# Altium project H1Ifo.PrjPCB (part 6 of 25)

## Sheet IfoIsc2A.SchDoc: D1800185
size C; Engineer: Daniel Sigg; DocumentNumber: 5; Revision: 4; SheetNumber: 5; SheetTotal: 11
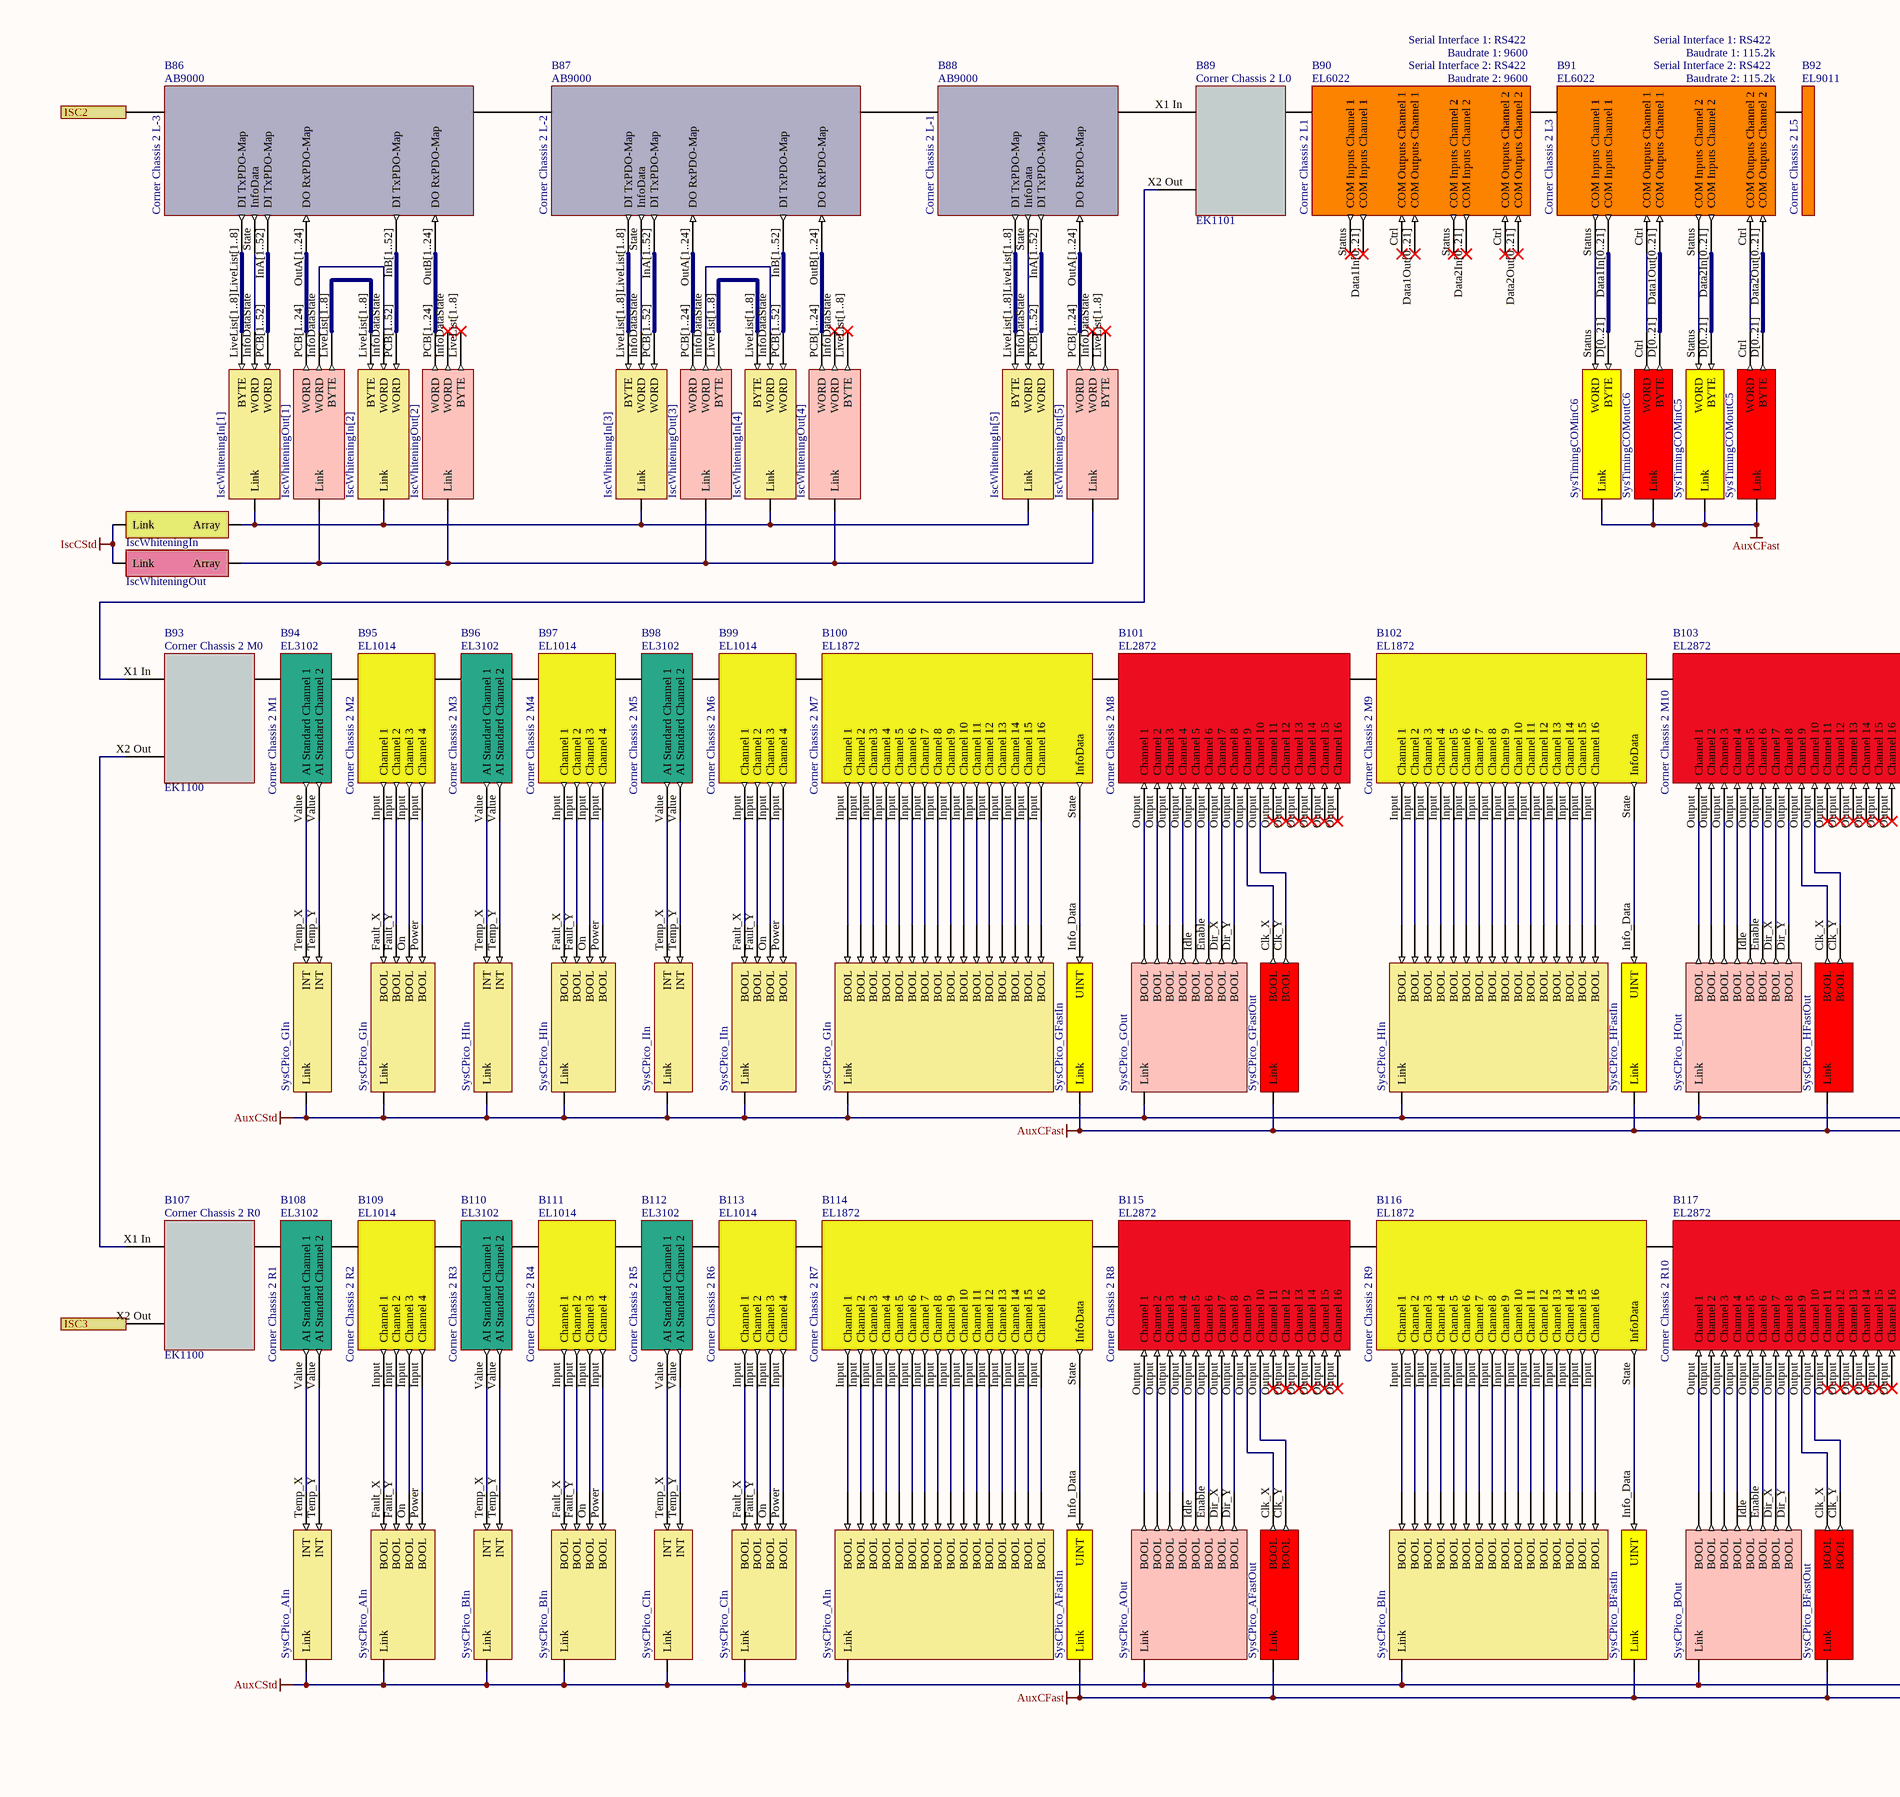
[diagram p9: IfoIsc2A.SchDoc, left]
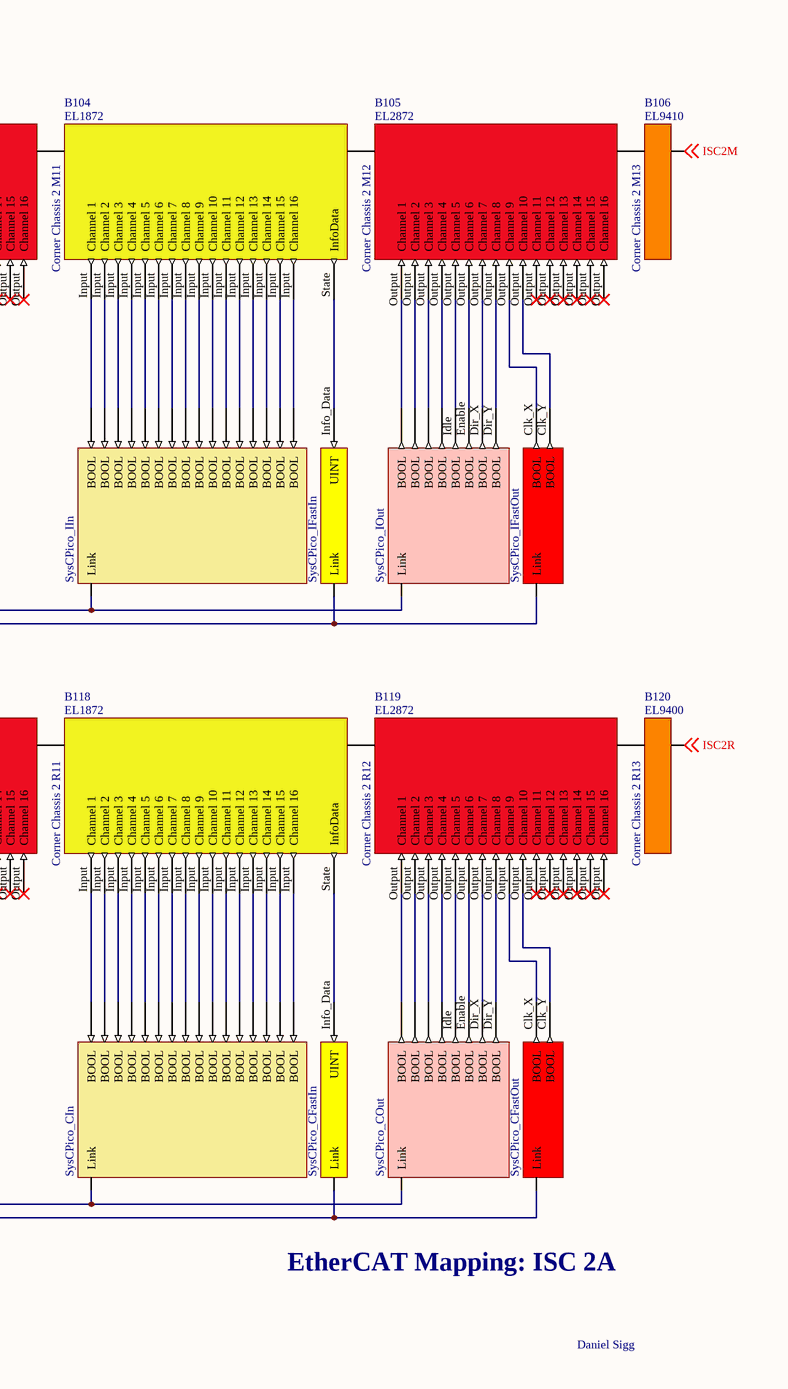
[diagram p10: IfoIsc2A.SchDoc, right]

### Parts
B86  Corner Chassis 2 L-3  Part Number: AB9000  (mechanical)
B87  Corner Chassis 2 L-2  Part Number: AB9000  (mechanical)
B88  Corner Chassis 2 L-1  Part Number: AB9000  (mechanical)
B89  Corner Chassis 2 L0  Part Number: EK1101  (mechanical)
B90  Corner Chassis 2 L1  Part Number: EL6022  Baudrate 1: 9600  Serial Interface 1: RS422  (mechanical)
B91  Corner Chassis 2 L3  Part Number: EL6022  Baudrate 1: 115.2k  Serial Interface 1: RS422  (mechanical)
B92  Corner Chassis 2 L5  Part Number: EL9011  (mechanical)
B93  Corner Chassis 2 M0  Part Number: EK1100  (mechanical)
B94  Corner Chassis 2 M1  Part Number: EL3102  (mechanical)
B95  Corner Chassis 2 M2  Part Number: EL1014  (mechanical)
B96  Corner Chassis 2 M3  Part Number: EL3102  (mechanical)
B97  Corner Chassis 2 M4  Part Number: EL1014  (mechanical)
B98  Corner Chassis 2 M5  Part Number: EL3102  (mechanical)
B99  Corner Chassis 2 M6  Part Number: EL1014  (mechanical)
B100  Corner Chassis 2 M7  Part Number: EL1872  (mechanical)
B101  Corner Chassis 2 M8  Part Number: EL2872  (mechanical)
B102  Corner Chassis 2 M9  Part Number: EL1872  (mechanical)
B103  Corner Chassis 2 M10  Part Number: EL2872  (mechanical)
B104  Corner Chassis 2 M11  Part Number: EL1872  (mechanical)
B105  Corner Chassis 2 M12  Part Number: EL2872  (mechanical)
B106  Corner Chassis 2 M13  Part Number: EL9410  (mechanical)
B107  Corner Chassis 2 R0  Part Number: EK1100  (mechanical)
B108  Corner Chassis 2 R1  Part Number: EL3102  (mechanical)
B109  Corner Chassis 2 R2  Part Number: EL1014  (mechanical)
B110  Corner Chassis 2 R3  Part Number: EL3102  (mechanical)
B111  Corner Chassis 2 R4  Part Number: EL1014  (mechanical)
B112  Corner Chassis 2 R5  Part Number: EL3102  (mechanical)
B113  Corner Chassis 2 R6  Part Number: EL1014  (mechanical)
B114  Corner Chassis 2 R7  Part Number: EL1872  (mechanical)
B115  Corner Chassis 2 R8  Part Number: EL2872  (mechanical)
B116  Corner Chassis 2 R9  Part Number: EL1872  (mechanical)
B117  Corner Chassis 2 R10  Part Number: EL2872  (mechanical)
B118  Corner Chassis 2 R11  Part Number: EL1872  (mechanical)
B119  Corner Chassis 2 R12  Part Number: EL2872  (mechanical)
B120  Corner Chassis 2 R13  Part Number: EL9400  (mechanical)
V49  SysCPico_GIn  (parts A,B,C of 3)  (no BOM)
V50  SysCPico_HIn  (parts A,B,C of 3)  (no BOM)
V51  SysCPico_IIn  (parts A,B,C of 3)  (no BOM)
V62  SysCPico_AIn  (parts A,B,C of 3)  (no BOM)
V63  SysCPico_BIn  (parts A,B,C of 3)  (no BOM)
V64  SysCPico_CIn  (parts A,B,C of 3)  (no BOM)
V152  IscWhiteningIn[1]  (no BOM)
V155  IscWhiteningOut[1]  (no BOM)
V156  IscWhiteningIn[2]  (no BOM)
V157  IscWhiteningOut[2]  (no BOM)
V158  IscWhiteningIn[3]  (no BOM)
V159  IscWhiteningOut[3]  (no BOM)
V160  IscWhiteningIn[4]  (no BOM)
V161  IscWhiteningOut[4]  (no BOM)
V162  IscWhiteningIn[5]  (no BOM)
V163  IscWhiteningOut[5]  (no BOM)
V164  IscWhiteningIn  (no BOM)
V165  SysTimingCOMinC6  (no BOM)
V166  SysTimingCOMoutC6  (no BOM)
V167  SysTimingCOMinC5  (no BOM)
V168  SysTimingCOMoutC5  (no BOM)
V170  IscWhiteningOut  (no BOM)
V172  SysCPico_GFastIn  (no BOM)
V173  SysCPico_GOut  (no BOM)
V174  SysCPico_GFastOut  (no BOM)
V175  SysCPico_HFastIn  (no BOM)
V178  SysCPico_HOut  (no BOM)
V179  SysCPico_HFastOut  (no BOM)
V180  SysCPico_IFastIn  (no BOM)
V181  SysCPico_IOut  (no BOM)
V182  SysCPico_IFastOut  (no BOM)
V183  SysCPico_AFastIn  (no BOM)
V184  SysCPico_AOut  (no BOM)
V185  SysCPico_AFastOut  (no BOM)
V186  SysCPico_BFastIn  (no BOM)
V187  SysCPico_BOut  (no BOM)
V188  SysCPico_BFastOut  (no BOM)
V189  SysCPico_CFastIn  (no BOM)
V190  SysCPico_COut  (no BOM)
V191  SysCPico_CFastOut  (no BOM)

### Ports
ISC2, ISC3

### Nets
AuxCFast: V165.?1(Link) V166.?1(Link) V167.?1(Link) V168.?1(Link) V172.0(Link) V174.0(Link) V175.0(Link) V179.0(Link) V180.0(Link) V182.0(Link) V183.0(Link) V185.0(Link) V186.0(Link) V188.0(Link) V189.0(Link) V191.0(Link)
AuxCStd: V49.0(Link) V49.1(Link) V49.2(Link) V50.0(Link) V50.1(Link) V50.2(Link) V51.0(Link) V51.1(Link) V51.2(Link) V62.0(Link) V62.1(Link) V62.2(Link) V63.0(Link) V63.1(Link) V63.2(Link) V64.0(Link) V64.1(Link) V64.2(Link) V173.0(Link) V178.0(Link) V181.0(Link) V184.0(Link) V187.0(Link) V190.0(Link)
IscCStd: V164.?1(Link) V170.?1(Link)
ISC2M: B106.Ebus(B) ; off-sheet ISC2M
ISC2R: B120.Ebus(B) ; off-sheet ISC2R
NetB70_X2 Out: B86.?2(A) ; port ISC2
NetB86_?1: B86.?1(B) B87.?2(A)
NetB86_InA[1..52]: B86.InA[1..52](DI_TxPDO-Map) V152.PCB[1..52](WORD)
NetB86_InB[1..52]: B86.InB[1..52](DI_TxPDO-Map) V156.PCB[1..52](WORD)
NetB86_LiveList[1..8]: B86.LiveList[1..8](DI_TxPDO-Map) V152.LiveList[1..8](BYTE)
NetB86_OutA[1..24]: B86.OutA[1..24](DO_RxPDO-Map) V155.PCB[1..24](WORD)
NetB86_OutB[1..24]: B86.OutB[1..24](DO_RxPDO-Map) V157.PCB[1..24](WORD)
NetB86_State: B86.State(InfoData) V152.InfoDataState(WORD)
NetB87_?1: B87.?1(B) B88.?2(A)
NetB87_InA[1..52]: B87.InA[1..52](DI_TxPDO-Map) V158.PCB[1..52](WORD)
NetB87_InB[1..52]: B87.InB[1..52](DI_TxPDO-Map) V160.PCB[1..52](WORD)
NetB87_LiveList[1..8]: B87.LiveList[1..8](DI_TxPDO-Map) V158.LiveList[1..8](BYTE)
NetB87_OutA[1..24]: B87.OutA[1..24](DO_RxPDO-Map) V159.PCB[1..24](WORD)
NetB87_OutB[1..24]: B87.OutB[1..24](DO_RxPDO-Map) V161.PCB[1..24](WORD)
NetB87_State: B87.State(InfoData) V158.InfoDataState(WORD)
NetB88_?1: B88.?1(B) B89.X1_In(A)
NetB88_InA[1..52]: B88.InA[1..52](DI_TxPDO-Map) V162.PCB[1..52](WORD)
NetB88_LiveList[1..8]: B88.LiveList[1..8](DI_TxPDO-Map) V162.LiveList[1..8](BYTE)
NetB88_OutA[1..24]: B88.OutA[1..24](DO_RxPDO-Map) V163.PCB[1..24](WORD)
NetB88_State: B88.State(InfoData) V162.InfoDataState(WORD)
NetB89_Ebus: B89.Ebus(B) B90.Ebus(A)
NetB89_X2 Out: B89.X2_Out(C) B93.X1_In(A)
NetB90_Ebus: B90.Ebus(B) B91.Ebus(A)
NetB91_Ctrl: B91.Ctrl(COM_Outputs_Channel_1) V166.Ctrl(WORD)
NetB91_Ctrl: B91.Ctrl(COM_Outputs_Channel_2) V168.Ctrl(WORD)  [a separate net that carries the same name]
NetB91_Data1In[0..21]: B91.Data1In[0..21](COM_Inputs_Channel_1) V165.D[0..21](BYTE)
NetB91_Data1Out[0..21]: B91.Data1Out[0..21](COM_Outputs_Channel_1) V166.D[0..21](BYTE)
NetB91_Data2In[0..21]: B91.Data2In[0..21](COM_Inputs_Channel_2) V167.D[0..21](BYTE)
NetB91_Data2Out[0..21]: B91.Data2Out[0..21](COM_Outputs_Channel_2) V168.D[0..21](BYTE)
NetB91_Ebus: B91.Ebus(B) B92.Ebus(A)
NetB91_Status: B91.Status(COM_Inputs_Channel_1) V165.Status(WORD)
NetB91_Status: B91.Status(COM_Inputs_Channel_2) V167.Status(WORD)  [a separate net that carries the same name]
NetB93_Ebus: B93.Ebus(B) B94.Ebus(A)
NetB93_X2 Out: B93.X2_Out(C) B107.X1_In(A)
NetB94_Ebus: B94.Ebus(B) B95.Ebus(A)
NetB94_Value: B94.Value(AI_Standard_Channel_1) V49.Temp_X(INT)
NetB94_Value: B94.Value(AI_Standard_Channel_2) V49.Temp_Y(INT)  [a separate net that carries the same name]
NetB95_Ebus: B95.Ebus(B) B96.Ebus(A)
NetB95_Input: B95.Input(Channel_1) V49.Fault_X(BOOL)
NetB95_Input: B95.Input(Channel_2) V49.Fault_Y(BOOL)  [a separate net that carries the same name]
NetB95_Input: B95.Input(Channel_3) V49.On(BOOL)  [a separate net that carries the same name]
NetB95_Input: B95.Input(Channel_4) V49.Power(BOOL)  [a separate net that carries the same name]
NetB96_Ebus: B96.Ebus(B) B97.Ebus(A)
NetB96_Value: B96.Value(AI_Standard_Channel_1) V50.Temp_X(INT)
NetB96_Value: B96.Value(AI_Standard_Channel_2) V50.Temp_Y(INT)  [a separate net that carries the same name]
NetB97_Ebus: B97.Ebus(B) B98.Ebus(A)
NetB97_Input: B97.Input(Channel_1) V50.Fault_X(BOOL)
NetB97_Input: B97.Input(Channel_2) V50.Fault_Y(BOOL)  [a separate net that carries the same name]
NetB97_Input: B97.Input(Channel_3) V50.On(BOOL)  [a separate net that carries the same name]
NetB97_Input: B97.Input(Channel_4) V50.Power(BOOL)  [a separate net that carries the same name]
NetB98_Ebus: B98.Ebus(B) B99.Ebus(A)
NetB98_Value: B98.Value(AI_Standard_Channel_1) V51.Temp_X(INT)
NetB98_Value: B98.Value(AI_Standard_Channel_2) V51.Temp_Y(INT)  [a separate net that carries the same name]
NetB99_Ebus: B99.Ebus(B) B100.Ebus(A)
NetB99_Input: B99.Input(Channel_1) V51.Fault_X(BOOL)
NetB99_Input: B99.Input(Channel_2) V51.Fault_Y(BOOL)  [a separate net that carries the same name]
NetB99_Input: B99.Input(Channel_3) V51.On(BOOL)  [a separate net that carries the same name]
NetB99_Input: B99.Input(Channel_4) V51.Power(BOOL)  [a separate net that carries the same name]
NetB100_Ebus: B100.Ebus(B) B101.Ebus(A)
NetB100_Input: B100.Input(Channel_1) V49.MotorX1(BOOL)
NetB100_Input: B100.Input(Channel_2) V49.MotorX2(BOOL)  [a separate net that carries the same name]
NetB100_Input: B100.Input(Channel_3) V49.MotorX3(BOOL)  [a separate net that carries the same name]
NetB100_Input: B100.Input(Channel_4) V49.MotorX4(BOOL)  [a separate net that carries the same name]
NetB100_Input: B100.Input(Channel_5) V49.MotorX5(BOOL)  [a separate net that carries the same name]
NetB100_Input: B100.Input(Channel_6) V49.MotorX6(BOOL)  [a separate net that carries the same name]
NetB100_Input: B100.Input(Channel_7) V49.MotorX7(BOOL)  [a separate net that carries the same name]
NetB100_Input: B100.Input(Channel_8) V49.MotorX8(BOOL)  [a separate net that carries the same name]
NetB100_Input: B100.Input(Channel_9) V49.MotorY1(BOOL)  [a separate net that carries the same name]
NetB100_Input: B100.Input(Channel_10) V49.MotorY2(BOOL)  [a separate net that carries the same name]
NetB100_Input: B100.Input(Channel_11) V49.MotorY3(BOOL)  [a separate net that carries the same name]
NetB100_Input: B100.Input(Channel_12) V49.MotorY4(BOOL)  [a separate net that carries the same name]
NetB100_Input: B100.Input(Channel_13) V49.MotorY5(BOOL)  [a separate net that carries the same name]
NetB100_Input: B100.Input(Channel_14) V49.MotorY6(BOOL)  [a separate net that carries the same name]
NetB100_Input: B100.Input(Channel_15) V49.MotorY7(BOOL)  [a separate net that carries the same name]
NetB100_Input: B100.Input(Channel_16) V49.MotorY8(BOOL)  [a separate net that carries the same name]
NetB100_State: B100.State(InfoData) V172.Info_Data(UINT)
NetB101_Ebus: B101.Ebus(B) B102.Ebus(A)
NetB101_Output: B101.Output(Channel_1) V173.MOTOR3(BOOL)
NetB101_Output: B101.Output(Channel_2) V173.MOTOR2(BOOL)  [a separate net that carries the same name]
NetB101_Output: B101.Output(Channel_3) V173.MOTOR1(BOOL)  [a separate net that carries the same name]
NetB101_Output: B101.Output(Channel_4) V173.MOTOR4(BOOL)  [a separate net that carries the same name]
NetB101_Output: B101.Output(Channel_5) V173.Idle(BOOL)  [a separate net that carries the same name]
NetB101_Output: B101.Output(Channel_6) V173.Enable(BOOL)  [a separate net that carries the same name]
NetB101_Output: B101.Output(Channel_7) V173.Dir_X(BOOL)  [a separate net that carries the same name]
NetB101_Output: B101.Output(Channel_8) V173.Dir_Y(BOOL)  [a separate net that carries the same name]
NetB101_Output: B101.Output(Channel_9) V174.Clk_X(BOOL)  [a separate net that carries the same name]
NetB101_Output: B101.Output(Channel_10) V174.Clk_Y(BOOL)  [a separate net that carries the same name]
NetB102_Ebus: B102.Ebus(B) B103.Ebus(A)
NetB102_Input: B102.Input(Channel_1) V50.MotorX1(BOOL)
NetB102_Input: B102.Input(Channel_2) V50.MotorX2(BOOL)  [a separate net that carries the same name]
NetB102_Input: B102.Input(Channel_3) V50.MotorX3(BOOL)  [a separate net that carries the same name]
NetB102_Input: B102.Input(Channel_4) V50.MotorX4(BOOL)  [a separate net that carries the same name]
NetB102_Input: B102.Input(Channel_5) V50.MotorX5(BOOL)  [a separate net that carries the same name]
NetB102_Input: B102.Input(Channel_6) V50.MotorX6(BOOL)  [a separate net that carries the same name]
NetB102_Input: B102.Input(Channel_7) V50.MotorX7(BOOL)  [a separate net that carries the same name]
NetB102_Input: B102.Input(Channel_8) V50.MotorX8(BOOL)  [a separate net that carries the same name]
NetB102_Input: B102.Input(Channel_9) V50.MotorY1(BOOL)  [a separate net that carries the same name]
NetB102_Input: B102.Input(Channel_10) V50.MotorY2(BOOL)  [a separate net that carries the same name]
NetB102_Input: B102.Input(Channel_11) V50.MotorY3(BOOL)  [a separate net that carries the same name]
NetB102_Input: B102.Input(Channel_12) V50.MotorY4(BOOL)  [a separate net that carries the same name]
NetB102_Input: B102.Input(Channel_13) V50.MotorY5(BOOL)  [a separate net that carries the same name]
NetB102_Input: B102.Input(Channel_14) V50.MotorY6(BOOL)  [a separate net that carries the same name]
NetB102_Input: B102.Input(Channel_15) V50.MotorY7(BOOL)  [a separate net that carries the same name]
NetB102_Input: B102.Input(Channel_16) V50.MotorY8(BOOL)  [a separate net that carries the same name]
NetB102_State: B102.State(InfoData) V175.Info_Data(UINT)
NetB103_Ebus: B103.Ebus(B) B104.Ebus(A)
NetB103_Output: B103.Output(Channel_1) V178.MOTOR3(BOOL)
NetB103_Output: B103.Output(Channel_2) V178.MOTOR2(BOOL)  [a separate net that carries the same name]
NetB103_Output: B103.Output(Channel_3) V178.MOTOR1(BOOL)  [a separate net that carries the same name]
NetB103_Output: B103.Output(Channel_4) V178.MOTOR4(BOOL)  [a separate net that carries the same name]
NetB103_Output: B103.Output(Channel_5) V178.Idle(BOOL)  [a separate net that carries the same name]
NetB103_Output: B103.Output(Channel_6) V178.Enable(BOOL)  [a separate net that carries the same name]
NetB103_Output: B103.Output(Channel_7) V178.Dir_X(BOOL)  [a separate net that carries the same name]
NetB103_Output: B103.Output(Channel_8) V178.Dir_Y(BOOL)  [a separate net that carries the same name]
NetB103_Output: B103.Output(Channel_9) V179.Clk_X(BOOL)  [a separate net that carries the same name]
NetB103_Output: B103.Output(Channel_10) V179.Clk_Y(BOOL)  [a separate net that carries the same name]
NetB104_Ebus: B104.Ebus(B) B105.Ebus(A)
NetB104_Input: B104.Input(Channel_1) V51.MotorX1(BOOL)
NetB104_Input: B104.Input(Channel_2) V51.MotorX2(BOOL)  [a separate net that carries the same name]
NetB104_Input: B104.Input(Channel_3) V51.MotorX3(BOOL)  [a separate net that carries the same name]
NetB104_Input: B104.Input(Channel_4) V51.MotorX4(BOOL)  [a separate net that carries the same name]
NetB104_Input: B104.Input(Channel_5) V51.MotorX5(BOOL)  [a separate net that carries the same name]
NetB104_Input: B104.Input(Channel_6) V51.MotorX6(BOOL)  [a separate net that carries the same name]
NetB104_Input: B104.Input(Channel_7) V51.MotorX7(BOOL)  [a separate net that carries the same name]
NetB104_Input: B104.Input(Channel_8) V51.MotorX8(BOOL)  [a separate net that carries the same name]
NetB104_Input: B104.Input(Channel_9) V51.MotorY1(BOOL)  [a separate net that carries the same name]
NetB104_Input: B104.Input(Channel_10) V51.MotorY2(BOOL)  [a separate net that carries the same name]
NetB104_Input: B104.Input(Channel_11) V51.MotorY3(BOOL)  [a separate net that carries the same name]
NetB104_Input: B104.Input(Channel_12) V51.MotorY4(BOOL)  [a separate net that carries the same name]
NetB104_Input: B104.Input(Channel_13) V51.MotorY5(BOOL)  [a separate net that carries the same name]
NetB104_Input: B104.Input(Channel_14) V51.MotorY6(BOOL)  [a separate net that carries the same name]
NetB104_Input: B104.Input(Channel_15) V51.MotorY7(BOOL)  [a separate net that carries the same name]
NetB104_Input: B104.Input(Channel_16) V51.MotorY8(BOOL)  [a separate net that carries the same name]
NetB104_State: B104.State(InfoData) V180.Info_Data(UINT)
NetB105_Ebus: B105.Ebus(B) B106.Ebus(A)
NetB105_Output: B105.Output(Channel_1) V181.MOTOR3(BOOL)
NetB105_Output: B105.Output(Channel_2) V181.MOTOR2(BOOL)  [a separate net that carries the same name]
NetB105_Output: B105.Output(Channel_3) V181.MOTOR1(BOOL)  [a separate net that carries the same name]
NetB105_Output: B105.Output(Channel_4) V181.MOTOR4(BOOL)  [a separate net that carries the same name]
NetB105_Output: B105.Output(Channel_5) V181.Idle(BOOL)  [a separate net that carries the same name]
NetB105_Output: B105.Output(Channel_6) V181.Enable(BOOL)  [a separate net that carries the same name]
NetB105_Output: B105.Output(Channel_7) V181.Dir_X(BOOL)  [a separate net that carries the same name]
NetB105_Output: B105.Output(Channel_8) V181.Dir_Y(BOOL)  [a separate net that carries the same name]
NetB105_Output: B105.Output(Channel_9) V182.Clk_X(BOOL)  [a separate net that carries the same name]
NetB105_Output: B105.Output(Channel_10) V182.Clk_Y(BOOL)  [a separate net that carries the same name]
NetB107_Ebus: B107.Ebus(B) B108.Ebus(A)
NetB107_X2 Out: B107.X2_Out(C) ; port ISC3
NetB108_Ebus: B108.Ebus(B) B109.Ebus(A)
NetB108_Value: B108.Value(AI_Standard_Channel_1) V62.Temp_X(INT)
NetB108_Value: B108.Value(AI_Standard_Channel_2) V62.Temp_Y(INT)  [a separate net that carries the same name]
NetB109_Ebus: B109.Ebus(B) B110.Ebus(A)
NetB109_Input: B109.Input(Channel_1) V62.Fault_X(BOOL)
NetB109_Input: B109.Input(Channel_2) V62.Fault_Y(BOOL)  [a separate net that carries the same name]
NetB109_Input: B109.Input(Channel_3) V62.On(BOOL)  [a separate net that carries the same name]
NetB109_Input: B109.Input(Channel_4) V62.Power(BOOL)  [a separate net that carries the same name]
NetB110_Ebus: B110.Ebus(B) B111.Ebus(A)
NetB110_Value: B110.Value(AI_Standard_Channel_1) V63.Temp_X(INT)
NetB110_Value: B110.Value(AI_Standard_Channel_2) V63.Temp_Y(INT)  [a separate net that carries the same name]
NetB111_Ebus: B111.Ebus(B) B112.Ebus(A)
NetB111_Input: B111.Input(Channel_1) V63.Fault_X(BOOL)
NetB111_Input: B111.Input(Channel_2) V63.Fault_Y(BOOL)  [a separate net that carries the same name]
NetB111_Input: B111.Input(Channel_3) V63.On(BOOL)  [a separate net that carries the same name]
NetB111_Input: B111.Input(Channel_4) V63.Power(BOOL)  [a separate net that carries the same name]
NetB112_Ebus: B112.Ebus(B) B113.Ebus(A)
NetB112_Value: B112.Value(AI_Standard_Channel_1) V64.Temp_X(INT)
NetB112_Value: B112.Value(AI_Standard_Channel_2) V64.Temp_Y(INT)  [a separate net that carries the same name]
NetB113_Ebus: B113.Ebus(B) B114.Ebus(A)
NetB113_Input: B113.Input(Channel_1) V64.Fault_X(BOOL)
NetB113_Input: B113.Input(Channel_2) V64.Fault_Y(BOOL)  [a separate net that carries the same name]
NetB113_Input: B113.Input(Channel_3) V64.On(BOOL)  [a separate net that carries the same name]
NetB113_Input: B113.Input(Channel_4) V64.Power(BOOL)  [a separate net that carries the same name]
NetB114_Ebus: B114.Ebus(B) B115.Ebus(A)
NetB114_Input: B114.Input(Channel_1) V62.MotorX1(BOOL)
NetB114_Input: B114.Input(Channel_2) V62.MotorX2(BOOL)  [a separate net that carries the same name]
NetB114_Input: B114.Input(Channel_3) V62.MotorX3(BOOL)  [a separate net that carries the same name]
NetB114_Input: B114.Input(Channel_4) V62.MotorX4(BOOL)  [a separate net that carries the same name]
NetB114_Input: B114.Input(Channel_5) V62.MotorX5(BOOL)  [a separate net that carries the same name]
NetB114_Input: B114.Input(Channel_6) V62.MotorX6(BOOL)  [a separate net that carries the same name]
NetB114_Input: B114.Input(Channel_7) V62.MotorX7(BOOL)  [a separate net that carries the same name]
NetB114_Input: B114.Input(Channel_8) V62.MotorX8(BOOL)  [a separate net that carries the same name]
NetB114_Input: B114.Input(Channel_9) V62.MotorY1(BOOL)  [a separate net that carries the same name]
NetB114_Input: B114.Input(Channel_10) V62.MotorY2(BOOL)  [a separate net that carries the same name]
NetB114_Input: B114.Input(Channel_11) V62.MotorY3(BOOL)  [a separate net that carries the same name]
NetB114_Input: B114.Input(Channel_12) V62.MotorY4(BOOL)  [a separate net that carries the same name]
NetB114_Input: B114.Input(Channel_13) V62.MotorY5(BOOL)  [a separate net that carries the same name]
NetB114_Input: B114.Input(Channel_14) V62.MotorY6(BOOL)  [a separate net that carries the same name]
NetB114_Input: B114.Input(Channel_15) V62.MotorY7(BOOL)  [a separate net that carries the same name]
NetB114_Input: B114.Input(Channel_16) V62.MotorY8(BOOL)  [a separate net that carries the same name]
NetB114_State: B114.State(InfoData) V183.Info_Data(UINT)
NetB115_Ebus: B115.Ebus(B) B116.Ebus(A)
NetB115_Output: B115.Output(Channel_1) V184.MOTOR3(BOOL)
NetB115_Output: B115.Output(Channel_2) V184.MOTOR2(BOOL)  [a separate net that carries the same name]
NetB115_Output: B115.Output(Channel_3) V184.MOTOR1(BOOL)  [a separate net that carries the same name]
NetB115_Output: B115.Output(Channel_4) V184.MOTOR4(BOOL)  [a separate net that carries the same name]
NetB115_Output: B115.Output(Channel_5) V184.Idle(BOOL)  [a separate net that carries the same name]
NetB115_Output: B115.Output(Channel_6) V184.Enable(BOOL)  [a separate net that carries the same name]
NetB115_Output: B115.Output(Channel_7) V184.Dir_X(BOOL)  [a separate net that carries the same name]
NetB115_Output: B115.Output(Channel_8) V184.Dir_Y(BOOL)  [a separate net that carries the same name]
NetB115_Output: B115.Output(Channel_9) V185.Clk_X(BOOL)  [a separate net that carries the same name]
NetB115_Output: B115.Output(Channel_10) V185.Clk_Y(BOOL)  [a separate net that carries the same name]
NetB116_Ebus: B116.Ebus(B) B117.Ebus(A)
NetB116_Input: B116.Input(Channel_1) V63.MotorX1(BOOL)
NetB116_Input: B116.Input(Channel_2) V63.MotorX2(BOOL)  [a separate net that carries the same name]
NetB116_Input: B116.Input(Channel_3) V63.MotorX3(BOOL)  [a separate net that carries the same name]
NetB116_Input: B116.Input(Channel_4) V63.MotorX4(BOOL)  [a separate net that carries the same name]
NetB116_Input: B116.Input(Channel_5) V63.MotorX5(BOOL)  [a separate net that carries the same name]
NetB116_Input: B116.Input(Channel_6) V63.MotorX6(BOOL)  [a separate net that carries the same name]
NetB116_Input: B116.Input(Channel_7) V63.MotorX7(BOOL)  [a separate net that carries the same name]
NetB116_Input: B116.Input(Channel_8) V63.MotorX8(BOOL)  [a separate net that carries the same name]
NetB116_Input: B116.Input(Channel_9) V63.MotorY1(BOOL)  [a separate net that carries the same name]
NetB116_Input: B116.Input(Channel_10) V63.MotorY2(BOOL)  [a separate net that carries the same name]
NetB116_Input: B116.Input(Channel_11) V63.MotorY3(BOOL)  [a separate net that carries the same name]
NetB116_Input: B116.Input(Channel_12) V63.MotorY4(BOOL)  [a separate net that carries the same name]
NetB116_Input: B116.Input(Channel_13) V63.MotorY5(BOOL)  [a separate net that carries the same name]
NetB116_Input: B116.Input(Channel_14) V63.MotorY6(BOOL)  [a separate net that carries the same name]
NetB116_Input: B116.Input(Channel_15) V63.MotorY7(BOOL)  [a separate net that carries the same name]
NetB116_Input: B116.Input(Channel_16) V63.MotorY8(BOOL)  [a separate net that carries the same name]
NetB116_State: B116.State(InfoData) V186.Info_Data(UINT)
NetB117_Ebus: B117.Ebus(B) B118.Ebus(A)
NetB117_Output: B117.Output(Channel_1) V187.MOTOR3(BOOL)
NetB117_Output: B117.Output(Channel_2) V187.MOTOR2(BOOL)  [a separate net that carries the same name]
NetB117_Output: B117.Output(Channel_3) V187.MOTOR1(BOOL)  [a separate net that carries the same name]
NetB117_Output: B117.Output(Channel_4) V187.MOTOR4(BOOL)  [a separate net that carries the same name]
NetB117_Output: B117.Output(Channel_5) V187.Idle(BOOL)  [a separate net that carries the same name]
NetB117_Output: B117.Output(Channel_6) V187.Enable(BOOL)  [a separate net that carries the same name]
NetB117_Output: B117.Output(Channel_7) V187.Dir_X(BOOL)  [a separate net that carries the same name]
NetB117_Output: B117.Output(Channel_8) V187.Dir_Y(BOOL)  [a separate net that carries the same name]
NetB117_Output: B117.Output(Channel_9) V188.Clk_X(BOOL)  [a separate net that carries the same name]
NetB117_Output: B117.Output(Channel_10) V188.Clk_Y(BOOL)  [a separate net that carries the same name]
NetB118_Ebus: B118.Ebus(B) B119.Ebus(A)
NetB118_Input: B118.Input(Channel_1) V64.MotorX1(BOOL)
NetB118_Input: B118.Input(Channel_2) V64.MotorX2(BOOL)  [a separate net that carries the same name]
NetB118_Input: B118.Input(Channel_3) V64.MotorX3(BOOL)  [a separate net that carries the same name]
NetB118_Input: B118.Input(Channel_4) V64.MotorX4(BOOL)  [a separate net that carries the same name]
NetB118_Input: B118.Input(Channel_5) V64.MotorX5(BOOL)  [a separate net that carries the same name]
NetB118_Input: B118.Input(Channel_6) V64.MotorX6(BOOL)  [a separate net that carries the same name]
NetB118_Input: B118.Input(Channel_7) V64.MotorX7(BOOL)  [a separate net that carries the same name]
NetB118_Input: B118.Input(Channel_8) V64.MotorX8(BOOL)  [a separate net that carries the same name]
NetB118_Input: B118.Input(Channel_9) V64.MotorY1(BOOL)  [a separate net that carries the same name]
NetB118_Input: B118.Input(Channel_10) V64.MotorY2(BOOL)  [a separate net that carries the same name]
NetB118_Input: B118.Input(Channel_11) V64.MotorY3(BOOL)  [a separate net that carries the same name]
NetB118_Input: B118.Input(Channel_12) V64.MotorY4(BOOL)  [a separate net that carries the same name]
NetB118_Input: B118.Input(Channel_13) V64.MotorY5(BOOL)  [a separate net that carries the same name]
NetB118_Input: B118.Input(Channel_14) V64.MotorY6(BOOL)  [a separate net that carries the same name]
NetB118_Input: B118.Input(Channel_15) V64.MotorY7(BOOL)  [a separate net that carries the same name]
NetB118_Input: B118.Input(Channel_16) V64.MotorY8(BOOL)  [a separate net that carries the same name]
NetB118_State: B118.State(InfoData) V189.Info_Data(UINT)
NetB119_Ebus: B119.Ebus(B) B120.Ebus(A)
NetB119_Output: B119.Output(Channel_1) V190.MOTOR3(BOOL)
NetB119_Output: B119.Output(Channel_2) V190.MOTOR2(BOOL)  [a separate net that carries the same name]
NetB119_Output: B119.Output(Channel_3) V190.MOTOR1(BOOL)  [a separate net that carries the same name]
NetB119_Output: B119.Output(Channel_4) V190.MOTOR4(BOOL)  [a separate net that carries the same name]
NetB119_Output: B119.Output(Channel_5) V190.Idle(BOOL)  [a separate net that carries the same name]
NetB119_Output: B119.Output(Channel_6) V190.Enable(BOOL)  [a separate net that carries the same name]
NetB119_Output: B119.Output(Channel_7) V190.Dir_X(BOOL)  [a separate net that carries the same name]
NetB119_Output: B119.Output(Channel_8) V190.Dir_Y(BOOL)  [a separate net that carries the same name]
NetB119_Output: B119.Output(Channel_9) V191.Clk_X(BOOL)  [a separate net that carries the same name]
NetB119_Output: B119.Output(Channel_10) V191.Clk_Y(BOOL)  [a separate net that carries the same name]
NetV152_?1: V152.?1(Link) V156.?1(Link) V158.?1(Link) V160.?1(Link) V162.?1(Link) V164.?2(Array)
NetV155_?1: V155.?1(Link) V157.?1(Link) V159.?1(Link) V161.?1(Link) V163.?1(Link) V170.?2(Array)
NetV155_InfoDataState: V155.InfoDataState(WORD) V156.InfoDataState(WORD)
NetV155_LiveList[1..8]: V155.LiveList[1..8](BYTE) V156.LiveList[1..8](BYTE)
NetV159_InfoDataState: V159.InfoDataState(WORD) V160.InfoDataState(WORD)
NetV159_LiveList[1..8]: V159.LiveList[1..8](BYTE) V160.LiveList[1..8](BYTE)

Not connected (* = marked no-connect by the designer): B90 Ctrl(COM_Outputs_Channel_1)* Data1In[0..21](COM_Inputs_Channel_1)* Data1Out[0..21](COM_Outputs_Channel_1)* Data2In[0..21](COM_Inputs_Channel_2)* Data2Out[0..21](COM_Outputs_Channel_2)* Status(COM_Inputs_Channel_1)*; V157 InfoDataState(WORD)* LiveList[1..8](BYTE)*; V161 InfoDataState(WORD)* LiveList[1..8](BYTE)*; V163 InfoDataState(WORD)* LiveList[1..8](BYTE)*

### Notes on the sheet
- EtherCAT Mapping: ISC 2A
- Daniel Sigg

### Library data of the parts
B86 = Anybus X-gateway 2xBIO: EtherCAT Modbus gateway for 2xBIO; Part Revision: V0000001b_P0000001b_R0001000d; BoxType: Box; BoxNextB: YWMGLFXR; BoxPrev: YDVXWSMS; PortPrevFull: 1040/C; PortPrevShort: C 'X2 Out'; Fullname: TIID^Vertex ISC (EtherCAT)^Corner Chassis 2 L-3 (AB9000); BoxAddr: 1053; PDO Inputs: 0x1A02; PDO Outputs: 0x1602; Disabled: False
B87 = Anybus X-gateway 2xBIO: EtherCAT Modbus gateway for 2xBIO; Part Revision: V0000001b_P0000001b_R0001000d; BoxType: Box; BoxNextB: YCOQNRPI; BoxPrev: PLVGYVWB; PortPrevFull: 1053/B; PortPrevShort: B; Fullname: TIID^Vertex ISC (EtherCAT)^Corner Chassis 2 L-2 (AB9000); BoxAddr: 1054; PDO Inputs: 0x1A02; PDO Outputs: 0x1602; Disabled: False
B88 = Anybus X-gateway 1xBIO: EtherCAT Modbus gateway for 1xBIO; Part Revision: V0000001b_P0000001b_R0001000d; BoxType: Box; BoxNextB: WSVAUKKE; BoxPrev: YWMGLFXR; PortPrevFull: 1054/B; PortPrevShort: B; Fullname: TIID^Vertex ISC (EtherCAT)^Corner Chassis 2 L-1 (AB9000); BoxAddr: 1055; PDO Inputs: 0x1A01; PDO Outputs: 0x1601; Disabled: False
B89 = CouplerEK1101: EtherCAT Coupler; Rail: Left; BoxNextB: IBHIBVAF; BoxNextC: QXDLEAUX; BoxPrev: YCOQNRPI; PortPrevFull: 1055/B; PortPrevShort: B; Fullname: TIID^Vertex ISC (EtherCAT)^Corner Chassis 2 L0 (EK1101); BoxPorts: Junction; BoxAddr: 1056; Disabled: False
B90 = TerminalEL6022: EtherCAT Terminal EL6022 Dual RS422; Rail: Left; BoxNextB: EDSXIWMO; BoxPrev: WSVAUKKE; PortPrevFull: 1056/B; PortPrevShort: B; Fullname: TIID^Vertex ISC (EtherCAT)^Corner Chassis 2 L0 (EK1101)^Corner Chassis 2 L1 (EL6022); BoxAddr: 1057; BoxSubType: 9103; Disabled: False
B91 = TerminalEL6022: EtherCAT Terminal EL6022 Dual RS422; Rail: Left; BoxNextB: HLLQDYWJ; BoxPrev: IBHIBVAF; PortPrevFull: 1057/B; PortPrevShort: B; Fullname: TIID^Vertex ISC (EtherCAT)^Corner Chassis 2 L0 (EK1101)^Corner Chassis 2 L3 (EL6022); BoxAddr: 1058; BoxSubType: 9103; Disabled: False
B92 = TerminalEL9011: EtherCAT Terminal EL9011 End; BoxType: TerminalPassive; Rail: Left; BoxPrev: EDSXIWMO; PortPrevShort: B; Fullname: TIID^Vertex ISC (EtherCAT)^Corner Chassis 2 L0 (EK1101)^Corner Chassis 2 L5 (EL9011); Disabled: False
B93 = CouplerEK1100: EtherCAT Coupler; Rail: Middle; BoxNextB: QBYDOCWK; BoxNextC: JDBXWTJH; BoxPrev: WSVAUKKE; PortPrevFull: 1056/C; PortPrevShort: C 'X2 Out'; Fullname: TIID^Vertex ISC (EtherCAT)^Corner Chassis 2 M0 (EK1100); BoxPorts: Junction; BoxAddr: 1059; Disabled: False
B94 = TerminalEL3102: EtherCAT Terminal EL3102 2-chn Analog Input; Rail: Middle; BoxNextB: GKVGUHYJ; BoxPrev: QXDLEAUX; PortPrevFull: 1059/B; PortPrevShort: B; Fullname: TIID^Vertex ISC (EtherCAT)^Corner Chassis 2 M0 (EK1100)^Corner Chassis 2 M1 (EL3102); BoxAddr: 1060; Disabled: False
B95 = TerminalEL1014: EtherCAT Terminal EL1014 4-channel digital input terminal 24 V DC; Rail: Middle; BoxNextB: AVLBWKIL; BoxPrev: QBYDOCWK; PortPrevFull: 1060/B; PortPrevShort: B; Fullname: TIID^Vertex ISC (EtherCAT)^Corner Chassis 2 M0 (EK1100)^Corner Chassis 2 M2 (EL1014); BoxAddr: 1061; Disabled: False
B96 = TerminalEL3102: EtherCAT Terminal EL3102 2-chn Analog Input; Rail: Middle; BoxNextB: GEPKCMFP; BoxPrev: GKVGUHYJ; PortPrevFull: 1061/B; PortPrevShort: B; Fullname: TIID^Vertex ISC (EtherCAT)^Corner Chassis 2 M0 (EK1100)^Corner Chassis 2 M3 (EL3102); BoxAddr: 1062; Disabled: False
B97 = TerminalEL1014: EtherCAT Terminal EL1014 4-channel digital input terminal 24 V DC; Rail: Middle; BoxNextB: LCKOMSKS; BoxPrev: AVLBWKIL; PortPrevFull: 1062/B; PortPrevShort: B; Fullname: TIID^Vertex ISC (EtherCAT)^Corner Chassis 2 M0 (EK1100)^Corner Chassis 2 M4 (EL1014); BoxAddr: 1063; Disabled: False
B98 = TerminalEL3102: EtherCAT Terminal EL3102 2-chn Analog Input; Rail: Middle; BoxNextB: JICPIUDK; BoxPrev: GEPKCMFP; PortPrevFull: 1063/B; PortPrevShort: B; Fullname: TIID^Vertex ISC (EtherCAT)^Corner Chassis 2 M0 (EK1100)^Corner Chassis 2 M5 (EL3102); BoxAddr: 1064; Disabled: False
B99 = TerminalEL1014: EtherCAT Terminal EL1014 4-channel digital input terminal 24 V DC; Rail: Middle; BoxNextB: FEYJKJKR; BoxPrev: LCKOMSKS; PortPrevFull: 1064/B; PortPrevShort: B; Fullname: TIID^Vertex ISC (EtherCAT)^Corner Chassis 2 M0 (EK1100)^Corner Chassis 2 M6 (EL1014); BoxAddr: 1065; Disabled: False
B100 = TerminalEL1872InfoData: EtherCAT Terminal EL1872 16-channel digital input terminal 24 V DC; Rail: Middle; BoxNextB: ATEQNOKE; BoxPrev: JICPIUDK; PortPrevFull: 1065/B; PortPrevShort: B; Fullname: TIID^Vertex ISC (EtherCAT)^Corner Chassis 2 M0 (EK1100)^Corner Chassis 2 M7 (EL1872); BoxAddr: 1066; Disabled: False
B101 = TerminalEL2872: EtherCAT Terminal EL2872 16-channel digital output terminal 24 V DC; Rail: Middle; BoxNextB: HFQLHLRI; BoxPrev: FEYJKJKR; PortPrevFull: 1066/B; PortPrevShort: B; Fullname: TIID^Vertex ISC (EtherCAT)^Corner Chassis 2 M0 (EK1100)^Corner Chassis 2 M8 (EL2872); BoxAddr: 1067; Disabled: False
B102 = TerminalEL1872InfoData: EtherCAT Terminal EL1872 16-channel digital input terminal 24 V DC; Rail: Middle; BoxNextB: HIXOIRLA; BoxPrev: ATEQNOKE; PortPrevFull: 1067/B; PortPrevShort: B; Fullname: TIID^Vertex ISC (EtherCAT)^Corner Chassis 2 M0 (EK1100)^Corner Chassis 2 M9 (EL1872); BoxAddr: 1068; Disabled: False
B103 = TerminalEL2872: EtherCAT Terminal EL2872 16-channel digital output terminal 24 V DC; Rail: Middle; BoxNextB: WSMFYCRR; BoxPrev: HFQLHLRI; PortPrevFull: 1068/B; PortPrevShort: B; Fullname: TIID^Vertex ISC (EtherCAT)^Corner Chassis 2 M0 (EK1100)^Corner Chassis 2 M10 (EL2872); BoxAddr: 1069; Disabled: False
B104 = TerminalEL1872InfoData: EtherCAT Terminal EL1872 16-channel digital input terminal 24 V DC; Rail: Middle; BoxNextB: DUUSWQAM; BoxPrev: HIXOIRLA; PortPrevFull: 1069/B; PortPrevShort: B; Fullname: TIID^Vertex ISC (EtherCAT)^Corner Chassis 2 M0 (EK1100)^Corner Chassis 2 M11 (EL1872); BoxAddr: 1070; Disabled: False
B105 = TerminalEL2872: EtherCAT Terminal EL2872 16-channel digital output terminal 24 V DC; Rail: Middle; BoxNextB: JSZGTQNB; BoxPrev: WSMFYCRR; PortPrevFull: 1070/B; PortPrevShort: B; Fullname: TIID^Vertex ISC (EtherCAT)^Corner Chassis 2 M0 (EK1100)^Corner Chassis 2 M12 (EL2872); BoxAddr: 1071; Disabled: False
B106 = TerminalEL9410: EtherCAT Terminal EL9410 Power; Rail: Middle; BoxNextB: RZQPCZGX; BoxPrev: DUUSWQAM; PortPrevFull: 1071/B; PortPrevShort: B; Fullname: TIID^Vertex ISC (EtherCAT)^Corner Chassis 2 M0 (EK1100)^Corner Chassis 2 M13 (EL9410); BoxAddr: 1072; Disabled: False
B107 = CouplerEK1100: EtherCAT Coupler; Rail: Right; BoxNextB: VOAQRNAB; BoxNextC: OSFIYXRO; BoxPrev: QXDLEAUX; PortPrevFull: 1059/C; PortPrevShort: C 'X2 Out'; Fullname: TIID^Vertex ISC (EtherCAT)^Corner Chassis 2 R0 (EK1100); BoxPorts: Junction; BoxAddr: 1085; Disabled: False
B108 = TerminalEL3102: EtherCAT Terminal EL3102 2-chn Analog Input; Rail: Right; BoxNextB: XFYEGUTX; BoxPrev: JDBXWTJH; PortPrevFull: 1085/B; PortPrevShort: B; Fullname: TIID^Vertex ISC (EtherCAT)^Corner Chassis 2 R0 (EK1100)^Corner Chassis 2 R1 (EL3102); BoxAddr: 1086; Disabled: False
B109 = TerminalEL1014: EtherCAT Terminal EL1014 4-channel digital input terminal 24 V DC; Rail: Right; BoxNextB: COSVFDFI; BoxPrev: VOAQRNAB; PortPrevFull: 1086/B; PortPrevShort: B; Fullname: TIID^Vertex ISC (EtherCAT)^Corner Chassis 2 R0 (EK1100)^Corner Chassis 2 R2 (EL1014); BoxAddr: 1087; Disabled: False
B110 = TerminalEL3102: EtherCAT Terminal EL3102 2-chn Analog Input; Rail: Right; BoxNextB: YFABUJKX; BoxPrev: XFYEGUTX; PortPrevFull: 1087/B; PortPrevShort: B; Fullname: TIID^Vertex ISC (EtherCAT)^Corner Chassis 2 R0 (EK1100)^Corner Chassis 2 R3 (EL3102); BoxAddr: 1088; Disabled: False
B111 = TerminalEL1014: EtherCAT Terminal EL1014 4-channel digital input terminal 24 V DC; Rail: Right; BoxNextB: YGYQANHA; BoxPrev: COSVFDFI; PortPrevFull: 1088/B; PortPrevShort: B; Fullname: TIID^Vertex ISC (EtherCAT)^Corner Chassis 2 R0 (EK1100)^Corner Chassis 2 R4 (EL1014); BoxAddr: 1089; Disabled: False
B112 = TerminalEL3102: EtherCAT Terminal EL3102 2-chn Analog Input; Rail: Right; BoxNextB: EPUDAUQU; BoxPrev: YFABUJKX; PortPrevFull: 1089/B; PortPrevShort: B; Fullname: TIID^Vertex ISC (EtherCAT)^Corner Chassis 2 R0 (EK1100)^Corner Chassis 2 R5 (EL3102); BoxAddr: 1090; Disabled: False
B113 = TerminalEL1014: EtherCAT Terminal EL1014 4-channel digital input terminal 24 V DC; Rail: Right; BoxNextB: ORSESUKS; BoxPrev: YGYQANHA; PortPrevFull: 1090/B; PortPrevShort: B; Fullname: TIID^Vertex ISC (EtherCAT)^Corner Chassis 2 R0 (EK1100)^Corner Chassis 2 R6 (EL1014); BoxAddr: 1091; Disabled: False
B114 = TerminalEL1872InfoData: EtherCAT Terminal EL1872 16-channel digital input terminal 24 V DC; Rail: Right; BoxNextB: XQTVNFTX; BoxPrev: EPUDAUQU; PortPrevFull: 1091/B; PortPrevShort: B; Fullname: TIID^Vertex ISC (EtherCAT)^Corner Chassis 2 R0 (EK1100)^Corner Chassis 2 R7 (EL1872); BoxAddr: 1092; Disabled: False
B115 = TerminalEL2872: EtherCAT Terminal EL2872 16-channel digital output terminal 24 V DC; Rail: Right; BoxNextB: RVACMMBM; BoxPrev: ORSESUKS; PortPrevFull: 1092/B; PortPrevShort: B; Fullname: TIID^Vertex ISC (EtherCAT)^Corner Chassis 2 R0 (EK1100)^Corner Chassis 2 R8 (EL2872); BoxAddr: 1093; Disabled: False
B116 = TerminalEL1872InfoData: EtherCAT Terminal EL1872 16-channel digital input terminal 24 V DC; Rail: Right; BoxNextB: HMWUSRUO; BoxPrev: XQTVNFTX; PortPrevFull: 1093/B; PortPrevShort: B; Fullname: TIID^Vertex ISC (EtherCAT)^Corner Chassis 2 R0 (EK1100)^Corner Chassis 2 R9 (EL1872); BoxAddr: 1094; Disabled: False
B117 = TerminalEL2872: EtherCAT Terminal EL2872 16-channel digital output terminal 24 V DC; Rail: Right; BoxNextB: VXENYIDU; BoxPrev: RVACMMBM; PortPrevFull: 1094/B; PortPrevShort: B; Fullname: TIID^Vertex ISC (EtherCAT)^Corner Chassis 2 R0 (EK1100)^Corner Chassis 2 R10 (EL2872); BoxAddr: 1095; Disabled: False
B118 = TerminalEL1872InfoData: EtherCAT Terminal EL1872 16-channel digital input terminal 24 V DC; Rail: Right; BoxNextB: RXKSSJMJ; BoxPrev: HMWUSRUO; PortPrevFull: 1095/B; PortPrevShort: B; Fullname: TIID^Vertex ISC (EtherCAT)^Corner Chassis 2 R0 (EK1100)^Corner Chassis 2 R11 (EL1872); BoxAddr: 1096; Disabled: False
B119 = TerminalEL2872: EtherCAT Terminal EL2872 16-channel digital output terminal 24 V DC; Rail: Right; BoxNextB: HMDXXCBQ; BoxPrev: VXENYIDU; PortPrevFull: 1096/B; PortPrevShort: B; Fullname: TIID^Vertex ISC (EtherCAT)^Corner Chassis 2 R0 (EK1100)^Corner Chassis 2 R12 (EL2872); BoxAddr: 1097; Disabled: False
B120 = TerminalEL9400: EtherCAT Terminal EL9400 Power; BoxType: TerminalPassive; Rail: Right; BoxNextB: IOJGNFIR; BoxPrev: RXKSSJMJ; PortPrevShort: B; Fullname: TIID^Vertex ISC (EtherCAT)^Corner Chassis 2 R0 (EK1100)^Corner Chassis 2 R13 (EL9400); Disabled: False
V49-V51 V62-V64 = Picomotor_PicomotorInStruct: PicomotorInStruct; BoxType: Variable; Instance: H1AuxCorner Instance; PLC: H1AuxCorner; Task: AuxCStd
V152 V156 V158 V160 V162 = ISCWhitening_IscWhiteningInStruct: IscWhiteningInStruct; BoxType: Variable; Instance: H1IscCorner Instance; PLC: H1IscCorner; Task: IscCStd
V155 V157 V159 V161 V163 = ISCWhitening_IscWhiteningOutStruct: IscWhiteningOutStruct; BoxType: Variable; Instance: H1IscCorner Instance; PLC: H1IscCorner; Task: IscCStd
V164 = ArrayAggregatorIn: Array [1..5] Of IscWhiteningInStruct; Instance: H1IscCorner Instance; PLC: H1IscCorner; Task: IscCStd; Lower Bound: 1; Upper Bound: 5
V165 V167 = Serial_EL6inData22Bfast: EL6inData22B; PLC: H1AuxCorner; Task: AuxCFast; BoxType: Variable; Instance: H1AuxCorner Instance
V166 V168 = Serial_EL6outData22Bfast: EL6outData22B; PLC: H1AuxCorner; Task: AuxCFast; BoxType: Variable; Instance: H1AuxCorner Instance
V170 = ArrayAggregatorOut: Array [1..5] Of IscWhiteningOutStruct; Instance: H1IscCorner Instance; PLC: H1IscCorner; Task: IscCStd; Lower Bound: 1; Upper Bound: 5
V172 V175 V180 V183 V186 V189 = Picomotor_PicomotorFastInStruct: PicomotorFastInStruct; BoxType: Variable; Instance: H1AuxCorner Instance; PLC: H1AuxCorner; Task: AuxCFast
V173 V178 V181 V184 V187 V190 = Picomotor_PicomotorOutStruct: PicomotorOutStruct; BoxType: Variable; Instance: H1AuxCorner Instance; PLC: H1AuxCorner; Task: AuxCStd
V174 V179 V182 V185 V188 V191 = Picomotor_PicomotorFastOutStruct: PicomotorFastOutStruct; BoxType: Variable; Instance: H1AuxCorner Instance; PLC: H1AuxCorner; Task: AuxCFast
